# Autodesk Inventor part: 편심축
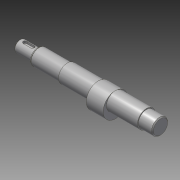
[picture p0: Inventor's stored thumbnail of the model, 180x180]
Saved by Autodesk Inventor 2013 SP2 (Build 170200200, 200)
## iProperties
Created: 2017-08
Part Number: 편심축
Material: 강철, 연강
Document SubType Name: Modeling
Designer: mduedu
Density: 1 g/cm^3
Author: mduedu
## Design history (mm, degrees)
sketch "스케치1"
  geometry: L1 (0, 0)-(150, 0); L2 (150, 0)-(150, 8.5); L3 (150, 8.5)-(135, 8.5); L4 (135, 8.5)-(135, 9.5); L5 (135, 9.5)-(51, 9.5); L6 (51, 9.5)-(51, 8.5); L7 (51, 8.5)-(19, 8.5); L8 (19, 8.5)-(19, 6); L9 (19, 6)-(0, 6); L10 (0, 6)-(0, 0)
  constraints: 20 end point, 6 parallel, 2 collinear, 2 perpendicular, 1 horizontal
  dimensions: "d0" = 150 distance of L1.start L1.end; "d1" = 17 diameter of L3 L1; "d2" = 19 diameter of L5 L1; "d3" = 12 diameter of L9 L1; "d4" = 19 distance of L8.end L9.end; "d5" = 15 distance of L2.end L3.end; "d6" = 84 distance of L4.end L5.end
revolve "회전1" sketch "스케치1" stored, may be unused: angle "d7" = 90 deg
node "작업 평면1"
sketch "스케치2"
  geometry: C1 r 9.5 at (0, 0) reference; C2 r 13 at (0, -3.5); 1 further point
  constraints: 1 centre point, 1 tangent, 1 vertical alignment
  dimensions: "d8" = 3.5 distance of point (0, 0) C2.centre
extrude "돌출1" join sketch "스케치2" stored distance "d9" = 18; taper "d10" = 0 deg
chamfer "모따기1" distance "d11" = 1; stored, may be unused: second distance "d12" = 2, angle "d13" = 45 deg
node "작업 평면2"
sketch "스케치3"
  geometry: L1 (3.5, -2)-(-4.5, -2); L2 (-4.5, -2)-(-4.5, 2); L3 (-4.5, 2)-(3.5, 2); L4 (3.5, 2)-(3.5, -2); L5 (9.5, 6)-(9.5, -6) reference; A1 r 2 centre (3.5, 0) between (3.5, -2) and (3.5, 2); A2 r 2 centre (-4.5, 0) between (-4.5, 2) and (-4.5, -2); A3 r 2 centre (3.5, 0) between (3.5, 2) and (3.5, -2); A4 r 2 centre (-4.5, 0) between (-4.5, -2) and (-4.5, 2); 1 further point
  constraints: 8 end point, 8 point on circle, 4 centre point, 2 midpoint, 2 parallel, 1 horizontal, 1 horizontal alignment, 1 perpendicular
  dimensions: "d14" = 12 dimension on A2 A1; "d16" = 4 distance between parallel lines of L3 L1; "d17" = 4 distance edge to line of A1 L5
extrude "돌출2" cut sketch "스케치3" distance "d18" = 2.5; taper "d19" = 0 deg
chamfer "모따기2" distance "d20" = 1; stored, may be unused: second distance "d21" = 2, angle "d22" = 45 deg
chamfer "모따기3" distance "d23" = 1; stored, may be unused: second distance "d24" = 2, angle "d25" = 60 deg
fillet "모깎기1" dims "d26" = 0.5
hole "구멍1" diameter "d29" = 3.242; stored, may be unused: countersink angle "d33" = 90 deg, drill point angle "d35" = 118 deg; dims "d30" = 8, "d31" = 4, "d32" = 2, "d34" = 10, "d48" = 10, "d49" = 10
sketch "스케치4"
  geometry: L1 (13.5, -6)-(15, -4.5); L2 (15, -4.5)-(16.5, -6); L3 (15, -6)-(13.5, -6); L4 (15, -6)-(15, -4.5); L5 (1, -6)-(19, -6) reference; L6 (19, -6)-(19, 6) reference; 1 further point
  constraints: 8 end point, 1 collinear, 1 horizontal, 1 point on line, 1 vertical, 1 other
  dimensions: "d42" = 4 distance between parallel lines of L6 L4; "d43" = 3 distance of L1.start L2.end; "d44" = 90 deg angle of L1 L2
revolve "회전2" sketch "스케치4" stored, may be unused: angle "d45" = 90 deg
node "작업점1"
node "솔리드1"
node "절단 모서리 투영1"
other parameters: "d38" = -42
